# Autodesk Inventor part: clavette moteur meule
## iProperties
Shininess: 64.0
Length Units: 11269
Angle Units: 11279
Time Units: 11290
Mass Units: 11283
Length Display Precision: 3
Angle Display Precision: 2
Compacted: True
Part Number: clavette moteur meule
Document SubType Name: Modeling
Created: 2005-01
Material: Par défaut
Designer: LEGERET Philippe
Density: 0.0
Volumn: 0.0
Area: 0.0
PropertySet Name: Model Information
Control State: 0
Master: False
Checked Out: False
Author: LEGERET Philippe
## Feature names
1. Extrusion1
